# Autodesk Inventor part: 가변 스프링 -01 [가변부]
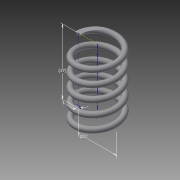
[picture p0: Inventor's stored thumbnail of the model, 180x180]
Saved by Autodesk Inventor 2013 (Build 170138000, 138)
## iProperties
Created: 2014-12
Part Number: 가변 스프링 -01 [가변부]
Material: Generic
Document SubType Name: Modeling
Designer: Administrator
Density: 1 g/cm^3
Mass: 2.38051 g
Surface Area: 32.3981 cm^2
Volume: 2.38051 cm^3
Author: Administrator
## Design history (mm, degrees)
sketch "Sketch1"
  geometry: L1 (0, 0)-(11, 0); L2 (11, 0)-(11, 25.208); L3 (11, 25.208)-(0, 25.208); L4 (0, 25.208)-(0, 0); C1 r 1.5 at (11, 0)
  constraints: 8 end point, 2 parallel, 1 centre point, 1 coincident, 1 horizontal, 1 perpendicular
  dimensions: "d0" = 3 diameter of C1; "d1" = 22 diameter of L2 L4; "d2" = 25.20829 distance between parallel lines of L1 L3 (derived)
coil "Coil1" pitch "d3" = 10; turns "d5" = 5; dims "d4" = 25.20829 (= d2), "d6" = 0, angle "d7" = 90 deg, angle "d8" = 90 deg, "d9" = 0, "d10" = 0
sketch "Sketch2"
  geometry: L1 (-12.5, 0)-(-9.5, 0) reference; 1 further point
  constraints: 1 horizontal alignment
extrude "Extrusion1" cut sketch "Sketch2" stored distance "d11" = 10; taper "d12" = 0 deg
workplane "Work Plane2"
sketch "Sketch3"
  geometry: L1 (1.5, 0)-(-1.5, 0) reference; 1 further point
  constraints: 1 horizontal alignment
extrude "Extrusion2" cut sketch "Sketch3" stored distance "d14" = 10; taper "d15" = 0 deg
body "Solid1"
node "Project Cut Edges1"
node "Project Cut Edges2"
other parameters: "d13" = 0
